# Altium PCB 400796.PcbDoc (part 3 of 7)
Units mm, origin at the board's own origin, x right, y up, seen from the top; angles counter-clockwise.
Board outline 53 x 53 mm, 6 copper layers (Top Layer, Mid Layer 1, Mid Layer 2, Mid Layer 3, Mid Layer 4, Bottom Layer), stack 1.494 mm thick; 319 components, 236 nets, 1249 pads, 2569 vias.
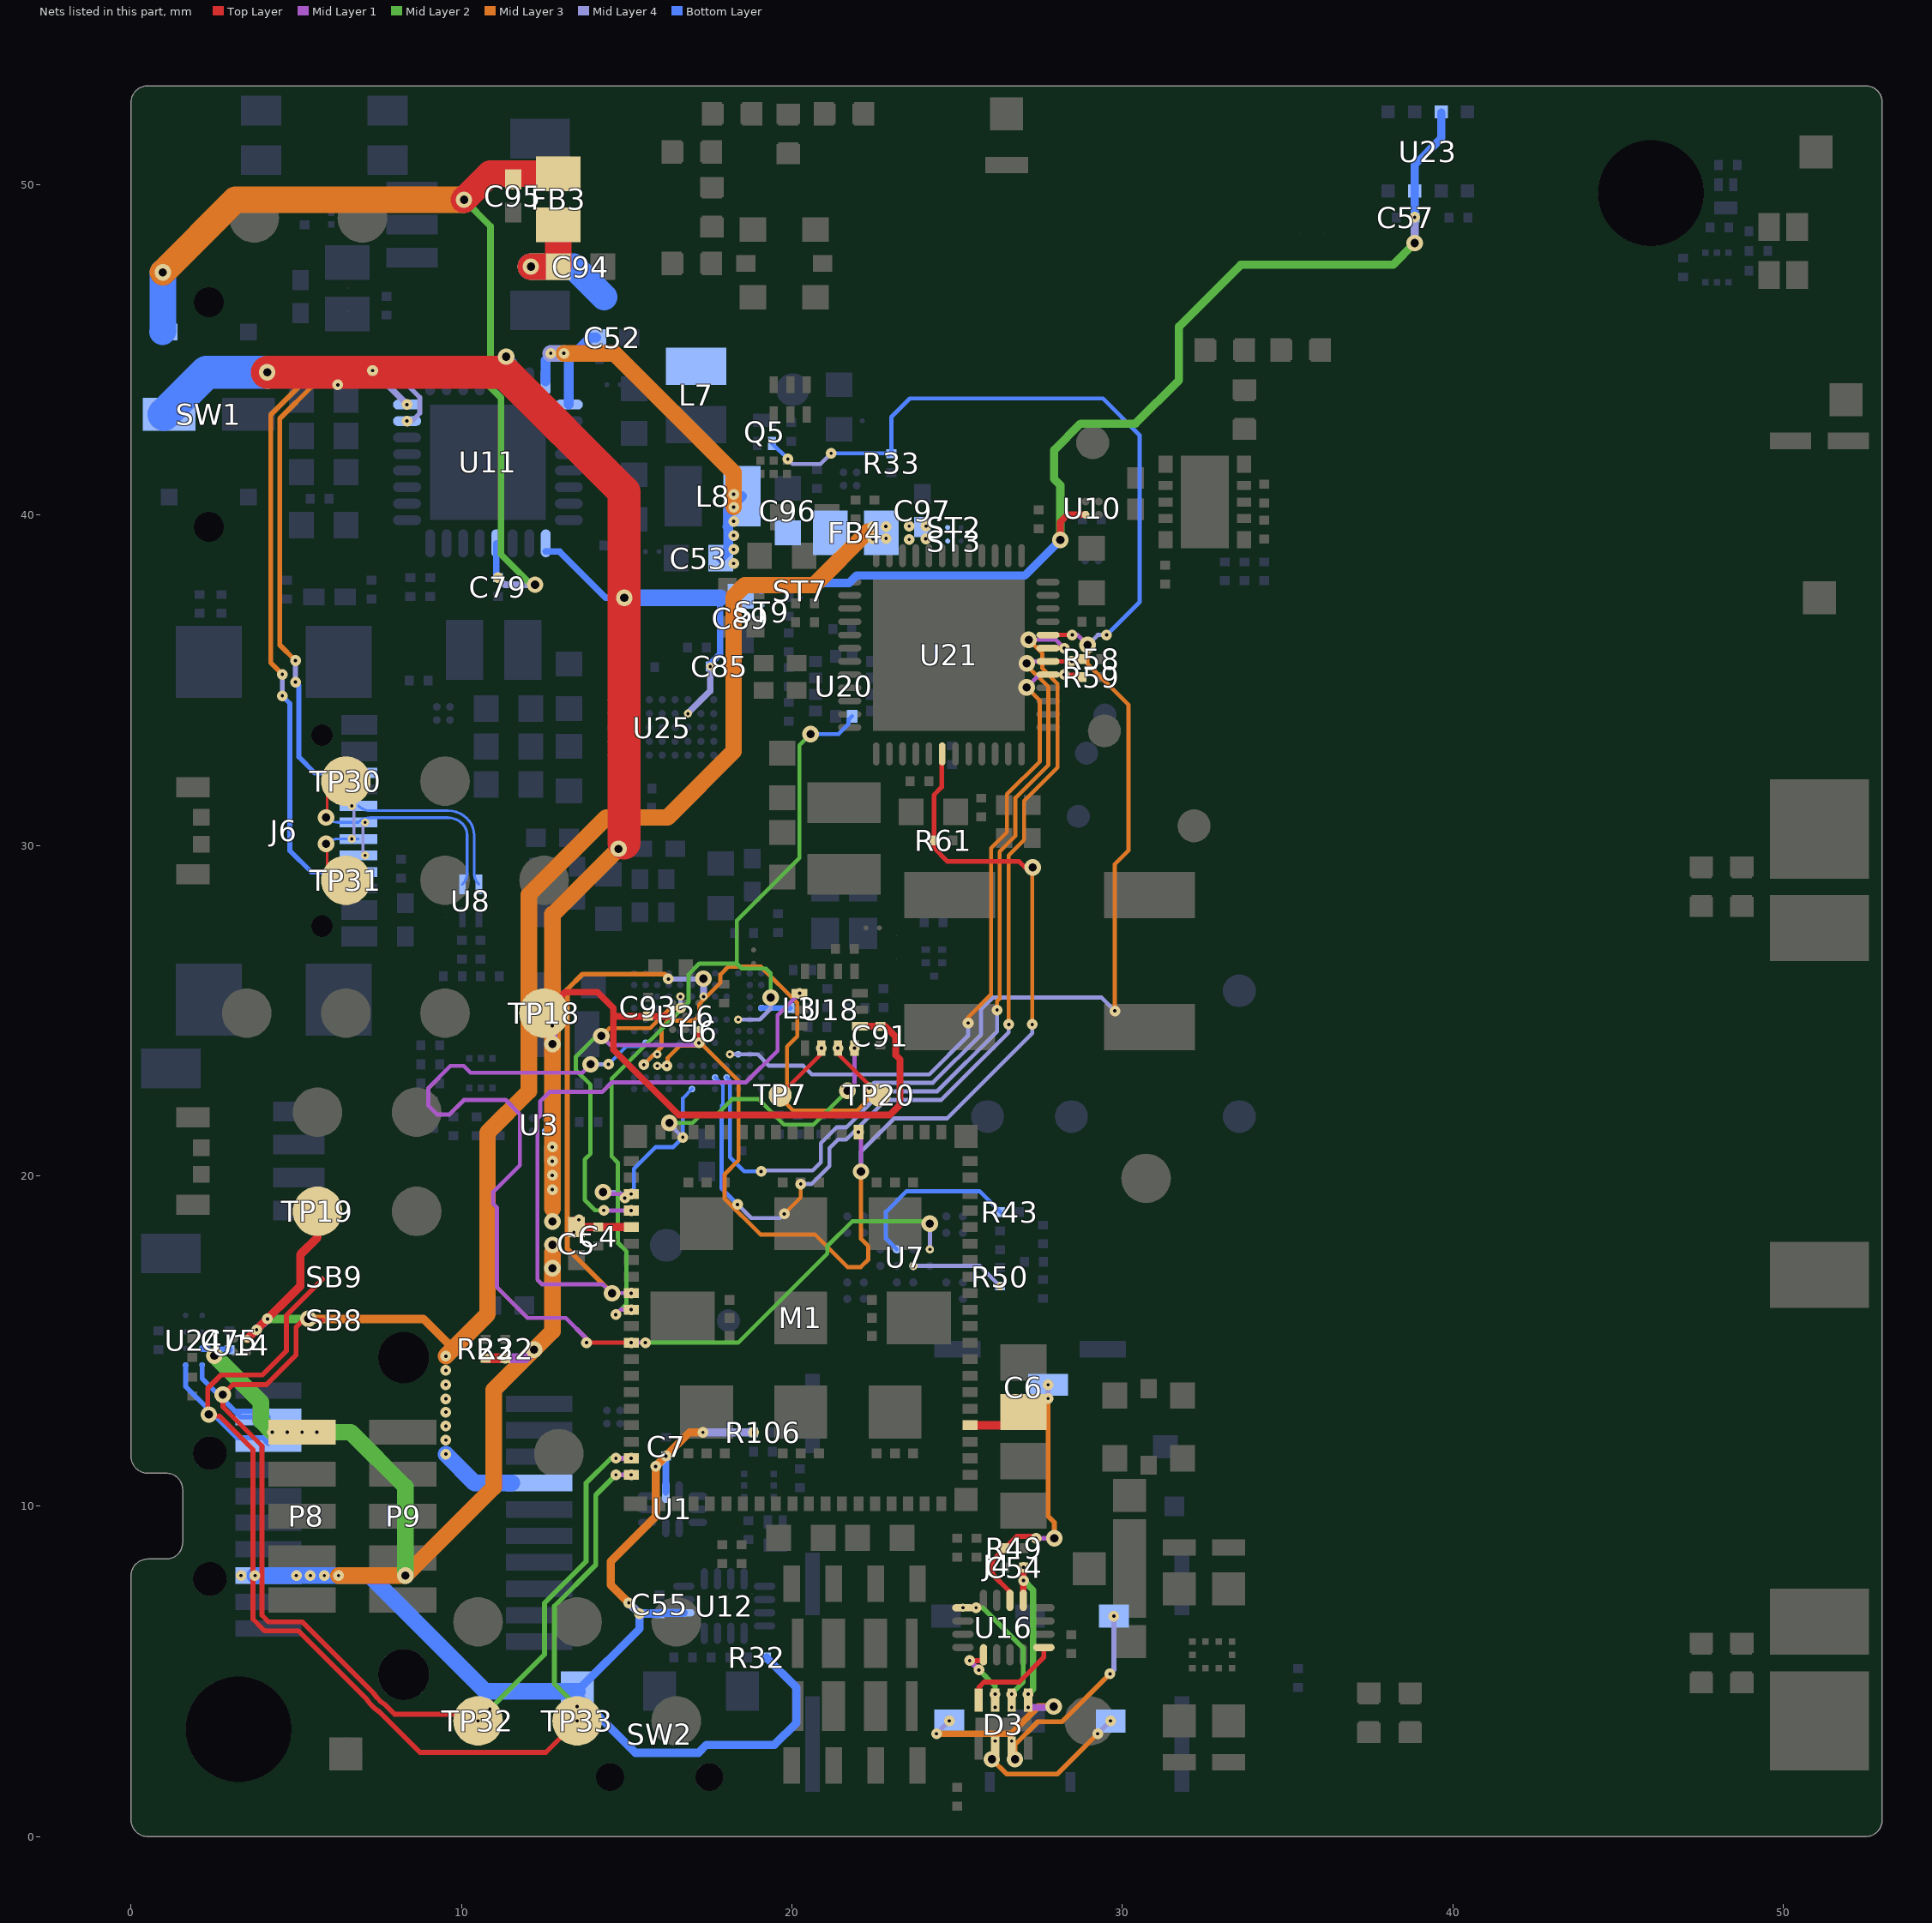
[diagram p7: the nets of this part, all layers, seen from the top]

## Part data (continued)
Z4 Z6: library part L0402-3n7-1950mA-30mΩ-LQW15AN3N7G80, "Inductor, 1950mA, ±2%, 30mΩ, Q=35", Manufacturer=Murata, Manufacturer Part Number=LQW15AN3N7G80D, Part number IPS=N.A., Part number NEMS=100300421, Supplier Part Number 1=81-LQW15AN3N7G80D
Z9: library part C0402-0.3p-HQ-Murata, "Capacitor, NP0, ±0.05pF, 50V", Manufacturer=Murata, Manufacturer Part Number=GJM1555C1HR30WB01D, Part number IPS=00000001777, Part number NEMS=100200433, Part number Norautron=N.A., Supplier Part Number 1=490-11248-1-ND
Z10: library part L0603-12n-750mA-71mΩ-LQW18AN12NG10, "Inductor, 750mA, ±2%, 71mΩ, Q=38", Manufacturer=Murata, Manufacturer Part Number=LQW18AN12NG10, Part number IPS=N.A., Part number NEMS=100300414, Supplier Part Number 1=490-6862-1-ND
Z11 Z32: library part C0402-N.C., "Not mounted", Manufacturer=N.A., Part number NEMS=100200105
Z12: library part L0402-N.C., "Not mounted", Manufacturer=N.A., Part number NEMS=100300037
Z21: library part L0402-2n8-1500mA-47mΩ-LQW15AN2N8G80, "Inductor, 1500mA, ±2%, 47mΩ, Q=27", Manufacturer=Murata, Manufacturer Part Number=LQW15AN2N8G80D, Part number IPS=N.A., Part number NEMS=100300422, Supplier Part Number 1=81-LQW15AN2N8G80D
Z22: library part L0402-2n5-Wirewound-Murata-LQW15AN2N5G80, "Inductor, 2100mA, ±2%, 30mΩ, Q=30", Manufacturer=Murata, Manufacturer Part Number=LQW15AN2N5G80D, Part number IPS=N.A., Part number NEMS=100300417, Supplier Part Number 1=LQW15AN2N5G80D-ND
Z31: library part L0402-3n8-Wirewound-Murata_HQ-LQW15AN3N8G80D, "3.8 nH Unshielded Drum Core, Wirewound Inductor 1.95 A 30mOhm Max 0402 (1005 Metric)", Manufacturer=Murata, Manufacturer Part Number=LQW15AN3N8G80D, Part number IPS=N.A., Part number NEMS=100300486, Supplier Part Number 1=490-LQW15AN3N8G80DTR-ND
Z33: library part L0402-9n0-Wirewound-Murata_HQ-LQW15AN6N0B80D, "6 nH Unshielded Drum Core, Wirewound Inductor 1.6 A 56mOhm Max 0402 (1005 Metric)", Manufacturer=Murata, Manufacturer Part Number=LQW15AN6N0B80D, Part number IPS=N.A., Part number NEMS=100300487, Supplier Part Number 1=490-17896-1-ND
Z34: library part C0402-0.4p-50V-NP0-GJM1555C1HR40WB01, "Capacitor, NP0, ±0.05pF, 50V", Manufacturer=Murata, Manufacturer Part Number=GJM1555C1HR40WB01D, Part number IPS=N.A., Part number NEMS=100200500, Supplier Part Number 1=490-11249-1-ND
Z35: library part C0402-1.8p-HQ-Murata, "Capacitor, C0G, ±0.05pF, 50V", Manufacturer=Murata, Manufacturer Part Number=GJM1555C1H1R8WB01D, Part number IPS=N.A., Part number NEMS=100200521, Supplier Part Number 1=490-11202-1-ND
Z36: library part L0603-N.C., "Not mounted", Manufacturer=N.A., Part number NEMS=100300069

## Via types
v1: diameter 0.325, hole 0.1, Mid Layer 4 to Bottom Layer, tented both sides, 675 vias
v2: diameter 0.325, hole 0.1, Top Layer to Mid Layer 1, tented both sides, 569 vias
v3: diameter 0.325, hole 0.1, Mid Layer 3 to Mid Layer 4, tented both sides, 384 vias
v4: diameter 0.5, hole 0.25, Mid Layer 1 to Mid Layer 4, tented both sides, 312 vias
v5: diameter 0.325, hole 0.1, Mid Layer 1 to Mid Layer 2, tented both sides, 265 vias
v6: diameter 0.5, hole 0.25, Top Layer to Bottom Layer, tented both sides, 175 vias
v7: diameter 0.25, hole 0.1, Mid Layer 4 to Bottom Layer, tented both sides, 105 vias
v8: diameter 0.325, hole 0.1, Top Layer to Mid Layer 1, tented top, 67 vias
v9: diameter 0.25, hole 0.1, Top Layer to Mid Layer 1, tented both sides, 17 vias

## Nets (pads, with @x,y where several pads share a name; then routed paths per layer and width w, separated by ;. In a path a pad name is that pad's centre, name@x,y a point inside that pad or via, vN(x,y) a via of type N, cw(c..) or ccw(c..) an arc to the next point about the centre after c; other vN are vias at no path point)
1V8: C79.1 C95.2 FB3.2 SW1.3 U11.12 | length 29.9
  Top Layer w0.8: v6(10.075,49.55) 10.866,50.341 FB3.2@12.931,50.341
  Mid Layer 2 w0.2: v6(10.075,49.55) 10.875,48.75 10.875,43.871 11.192,43.554 11.192,38.816 12.113,37.895 v4(12.226,37.895)
  Mid Layer 3 w0.8: v6(0.96,47.351) 3.159,49.55 v6(10.075,49.55)
  Mid Layer 4 w0.2: v1(11.1,38.11) 11.315,37.895 v4(12.226,37.895)
  Bottom Layer w0.2: C79.1@11.05,38.11 U11.12@11.05,39.15
  Bottom Layer w0.8: SW1.3@0.95,45.55 0.96,45.56 v6(0.96,47.351)
1V8_IND: C52.2 C94.2 FB3.1 L7.1 U11.1 | length 7.2
  Top Layer w0.8: v6(12.1,47.525) C94.2@12.931,47.525 FB3.1@12.931,48.791
  Bottom Layer w0.3: U11.1@13.25,43.35 13.25,44.723 13.904,45.377 C52.2@14.075,45.377
  Bottom Layer w0.8: v6(12.1,47.525) 13.4,47.525 14.318,46.607
1V8_SW: C4.1 C5.1 C7.1 C55.1 C57.2 C75.2 C85.1 C89.2 C91.2 C93.2 M1.65 P8.1 P9.3 R22.1 R23.1 R32.1 R106.1 ST7.1 ST9.1 SW1.2 SW2.3 TP18.1 U1.1 U3.A2 U10.A2 U11.9 U11.30 U12.14 U18.5 U23.2 U23.6 U24.C1 U25.C4 U26.B3 | length 166.2
  Top Layer w0.2: v6(28.125,39.25) 28.125,39.801 28.339,40.015 U10.A2@28.888,40.015
  Top Layer w0.203: TP18.1@12.5,24.927 13.135,25.563 14.117,25.563 14.596,25.084 14.596,24.835 ; C5.1@13.399,18.672 v2(13.552,18.672) ; C5.1@13.478,18.45 C5.1@13.478,18.523 ; U26.B3@16.388,24.831 C93.2@15.65,24.831 14.6,24.831 14.596,24.835 ; U18.5@22.056,24.529 C91.2@22.679,24.529 22.819,24.529 23.143,24.205 23.143,23.654 23.273,23.524 23.273,22.155 22.958,21.84 16.582,21.84 14.596,23.826 14.596,24.835
  Top Layer w0.25: C5.1@13.478,18.45 M1.65@15.142,18.45
  Top Layer w0.305: R23.1@10.723,14.48 v2(11.323,14.48) ; TP18.1@12.5,24.927 12.75,24.678 v2(12.75,24.542)
  Top Layer w1: v6(4.118,44.325) 11.3,44.325 14.925,40.7 v6(14.925,37.5) v6@14.925,30.075
  Mid Layer 1 w0.305: v2(11.323,14.48) 11.932,14.48 v4(12.193,14.741) ; v4(12.75,23.989) v2(12.75,24.542)
  Mid Layer 2 w0.25: v6(28.125,39.25) 28.125,40.908 27.939,41.094 27.939,41.972 28.737,42.77 30.4,42.77 31.714,44.084 31.714,45.711 33.586,47.583 38.194,47.583 v4(38.85,48.239)
  Mid Layer 2 w0.5: v6(2.518,14.561) 3.927,13.152 3.927,12.588 v5(4.275,12.24) v5(4.725,12.24) 6.646,12.24 8.3,10.586 v4(8.3,7.9)
  Mid Layer 3 w0.25: v3(15.062,7.075) 14.516,7.62 14.516,8.321 15.877,9.681 v3(15.877,11.206) 16.904,12.234 v3(17.307,12.234)
  Mid Layer 3 w0.5: v3(6.275,7.9) v4(8.3,7.9) 10.975,10.575 10.975,13.522 v4(12.193,14.741) 12.75,15.297 v4(12.75,17.202) v4@12.75,17.685 ; 12.75,19 12.75,27.925 ; 12.775,27.925 v6(14.75,29.9)
  Mid Layer 4 w0.2: v7@16.855,34.009 17.527,34.68 v7(17.527,35.42)
  Mid Layer 4 w0.25: v3(15.062,7.075) v1(15.386,6.75) ; v3(15.877,11.206) v1(16.186,11.516) ; v3(17.307,12.234) 17.309,12.232 v1(18.843,12.232) ; v4(38.85,48.239) v1(38.85,49.021)
  Bottom Layer w0.2: U11.9@12.55,38.9 12.964,38.9 14.364,37.5 v6(14.925,37.5) ; v7(17.527,35.42) 17.527,35.502 17.825,35.8 17.825,37.5
  Bottom Layer w0.203: U24.C1@2.15,14.775 2.304,14.775 v6(2.518,14.561) 2.698,14.74 C75.2@2.975,14.74 ; U1.1@16.186,10.425 v1(16.186,11.516)
  Bottom Layer w0.25: C55.1@16,6.75 v1(15.386,6.75) 15.386,6.286 SW2.3@13.5,4.4 13.5,4.298 15.265,2.534 17.17,2.534 17.412,2.775 19.471,2.775 20.137,3.442 20.137,4.512 R32.1@19.227,5.422 ; C55.1@16.05,6.775 U12.14@16.725,6.775 ; 19.073,37.734 19.289,37.949 21.728,37.949 21.958,38.18 27.055,38.18 v6(28.125,39.25) ; v1(38.85,49.021) U23.6@38.85,49.811 38.85,50.608 39.65,51.408 U23.2@39.65,52.195
  Bottom Layer w0.3: v6(11.35,44.8) 11.55,44.6 U11.30@11.55,44.05
  Bottom Layer w0.5: v1@12.75,20.45 v1(12.75,20.875) ; v6@14.95,37.5 17.825,37.5
  Bottom Layer w0.508: v1(3.75,7.9) P9.3@4.15,7.9 7.215,7.9 10.715,4.4 SW2.3@13.5,4.4
  Bottom Layer w1: SW1.2@1,43.05 2.275,44.325 v6(4.118,44.325)
  other v1: 3.325,7.9 12.75,19.585 12.75,20.015 12.75,20.445
  other v2: 5.175,12.24 5.625,12.24 13.401,18.293
  other v3: 5,7.9 5.425,7.9 5.85,7.9
  other v4: 12.75,17.912 12.75,18.621
  other v7: 16.855,33.995
2.4G_SW_CTRL: Q5.1 R33.2 U6.H10 U21.44 | length 56.5
  Top Layer w0.125: U21.44@27.75,36.375 v2(28.487,36.375)
  Mid Layer 1 w0.125: v2(28.487,36.375) 28.645,36.375 v4(28.95,36.07)
  Mid Layer 3 w0.125: v3(15.517,23.366) 16.059,23.907 16.059,24.496 16.262,24.699 17.048,24.699 17.193,24.844 17.193,25.199 17.836,25.842 17.836,26.098 18.071,26.334 19.063,26.334 20.164,25.233 20.164,24.227 19.85,23.913 19.85,22.161 20.032,21.98 21.976,21.98 22.337,22.341 v3(22.337,22.666) ; v4(28.95,36.07) 28.95,35.496 30.19,34.256 30.19,29.854 29.776,29.441 v3(29.776,24.994)
  Mid Layer 4 w0.125: v3(15.517,23.366) 15.831,23.68 v7(15.925,23.68) ; v1(19.875,41.7) 20.025,41.55 20.865,41.55 v1(21.189,41.874) ; v3(22.337,22.666) 22.49,22.819 24.268,22.819 25.725,24.275 25.725,25.042 26.079,25.396 29.374,25.396 v3(29.776,24.994) ; v4(28.95,36.07) 29.255,36.375 v1(29.525,36.375)
  Bottom Layer w0.125: Q5.1@19.4,42.175 v1(19.875,41.7) ; v1(21.189,41.874) 22.884,41.874 R33.2@22.935,41.824 ; R33.2@23.011,41.859 23.011,42.979 23.569,43.537 29.413,43.537 30.525,42.425 30.525,37.375 v1(29.525,36.375)
3V3: C97.2 FB4.2 P9.14 ST2.1 ST3.1 TP19.1 U14.A2 | length 46.2
  Top Layer w0.254: U14.A2@3.519,15.064 v2(3.797,15.342) 5.122,16.667 5.122,17.619 5.642,18.14 TP19.1@5.642,18.927
  Mid Layer 1 w0.254: v2(3.797,15.342) v5(4.125,15.67)
  Mid Layer 2 w0.254: v5(4.125,15.67) v4(5.361,15.67)
  Mid Layer 3 w0.254: v4(5.361,15.67) 8.848,15.67 9.747,14.772
  Mid Layer 3 w0.5: v3(9.525,14.54) 9.525,14.55 9.747,14.772 10.785,15.81 10.785,21.31 12.037,22.562 12.037,28.512 14.378,30.853 16.237,30.853 18.237,32.853 18.237,37.542 18.576,37.882 20.675,37.882 22.293,39.499 22.321,39.499
  Bottom Layer w0.5: v1(9.525,11.575) 10.4,10.7 P9.14@11.525,10.7
  other v1: 9.525,12 9.525,12.425 9.525,12.85 23.551,39.265 24.051,39.285 23.551,39.667 24.058,39.67
  other v3: 9.525,13.25 9.525,13.68 9.525,14.11 22.453,39.29 22.849,39.296 22.448,39.651 22.843,39.661
3V3_IND: C53.2 C96.2 FB4.1 L8.1 U11.32 | length 11.8
  Mid Layer 3 w0.5: v3(13.1,44.9) 14.625,44.9 18.237,41.288 v3(18.237,40.631) v3(18.237,40.244)
  Mid Layer 4 w0.5: v1(12.7,44.9) v3(13.1,44.9)
  Bottom Layer w0.3: U11.32@12.55,44.05 12.55,44.696 12.7,44.846 v1(12.7,44.9) ; C53.2@17.85,38.7 18.075,38.925 L8.1@18.075,40.165 ; 18.05,39.65 L8.1@18.07,39.67 ; 18.07,39.539 L8.1@18.07,39.67 ; L8.1@18.485,40.575 L8.1@18.075,40.165 ; L8.1@18.07,39.67 18.07,39.814 18.07,40.16 L8.1@18.075,40.165
  other v1: 18.237,38.538 18.237,38.964 18.237,39.389 18.237,39.814
4FF_1V8: C54.1 D3.5 J4.C1 U16.1 | length 10.6
  Top Layer w0.2: U16.1@27,7.15 C54.1@27,8.14
  Mid Layer 1 w0.15: v5(27.01,7.75) v2(27.01,8.15)
  Mid Layer 1 w0.2: v5(27.15,4.31) v9(27.15,3.91) v4@27.925,3.91
  Mid Layer 2 w0.2: v5(27.01,7.75) 27.3,7.46 27.3,4.46 v5(27.15,4.31)
  Mid Layer 3 w0.2: v3(24.376,3.111) 26.636,3.111 27.46,3.935 v4(27.925,3.935)
  Mid Layer 4 w0.15: v3(24.376,3.111) v1(24.765,3.5)
4FF_CLK: D3.7 U16.9 | length 2.3
  Top Layer w0.15: v2(25.38,5.325) 25.381,5.326 25.768,5.326 25.8,5.359 U16.9@25.8,5.5
  Mid Layer 1 w0.15: v2(25.38,5.325) v5(25.662,5.042) ; v9(26.15,3.91) v5(26.15,4.31)
  Mid Layer 2 w0.15: v5(25.662,5.042) 26.15,4.555 v5(26.15,4.31)
4FF_DETECT: J4.DSW R49.1 U16.2 | length 8.3
  Top Layer w0.15: R49.1@26.365,8.65 26.077,8.362 26.077,7.926 26.565,7.438 26.565,7.419 26.6,7.384 U16.2@26.6,7.15 ; R49.1@26.44,8.725 26.804,9.089 27.359,9.089 27.388,9.06 v2(27.388,9.028)
  Mid Layer 1 w0.15: v2(27.388,9.028) v4(27.941,9.028)
  Mid Layer 3 w0.15: v3(27.755,13.258) 27.755,9.696 27.941,9.511 v4(27.941,9.028)
  Mid Layer 4 w0.15: v3(27.755,13.258) v1(27.755,13.675)
4FF_IO: D3.6 U16.5 | length 4.3
  Mid Layer 1 w0.15: v9(25.175,6.925) v5(25.575,6.925) ; v9(26.65,3.91) v5(26.65,4.31)
  Mid Layer 2 w0.15: v5(25.575,6.925) 25.775,6.925 27,5.7 27,4.673 26.65,4.323 v5(26.65,4.31)
4FF_RST: D3.8 U16.13 | length 3.3
  Top Layer w0.15: D3.8@25.65,3.91 D3.8@25.65,4.125 25.65,4.51 25.815,4.675 26.875,4.675 27.625,5.425 U16.13@27.625,5.725
ADXL367_INT: M1.70 U6.E3 U20.5 | length 26.5
  Mid Layer 1 w0.125: v5(14.667,15.798) 14.82,15.95 v2(15.138,15.95)
  Mid Layer 2 w0.125: v5(14.667,15.798) 14.994,16.124 14.994,17.715 14.732,17.977 14.732,20.398 14.544,20.586 14.544,22.939 16.874,25.269 16.874,26.109 17.19,26.425 18.334,26.425 ; v4(19.359,25.4) 19.359,26.136 19.218,26.277 18.482,26.277 18.334,26.425 ; v6(20.561,33.375) 20.225,33.039 20.225,29.625 18.334,27.734 18.334,26.425
  Mid Layer 4 w0.125: v7(18.375,24.73) 19.026,24.73 19.359,25.063 v4(19.359,25.4)
  Bottom Layer w0.125: v6(20.561,33.375) 21.412,33.375 21.711,33.674 21.711,33.801 U20.5@21.825,33.915
ANT: L3.2 U6.D1 | length 0.9
  Bottom Layer w0.165: U6.D1@19.075,25.08 L3.2@19.939,25.08
ASCL: TP20.1 U18.3 | length 1.9
  Top Layer w0.125: v2(21.393,23.866) 21.393,23.694 TP20.1@22.643,22.444
ASDA: TP7.1 U18.2 | length 1.9
  Top Layer w0.125: TP7.1@19.643,22.444 20.893,23.694 v2(20.893,23.866)
BMI270_CS: M1.69 U6.C6 U18.12 | length 32.7
  Mid Layer 1 w0.125: v2(15.138,16.45) 14.556,16.45 v4(14.554,16.447) 14.285,16.715 12.437,16.715 12.297,16.854 12.297,21.738 12.387,21.827 12.387,22.263 12.666,22.542 14.256,22.542 14.544,22.83 18.608,22.83 19.568,23.789 19.568,24.866 v2(20.231,25.529)
  Mid Layer 2 w0.203: v4@17.167,25.971 v4@17.193,25.971
  Mid Layer 3 w0.152: v4(14.554,16.447) 13.201,17.799 13.201,25.646 13.663,26.108 16.139,26.108 16.159,26.088
  Mid Layer 4 w0.152: v3(16.261,25.961) 17.182,25.961 v4@17.193,25.971
  Mid Layer 4 w0.203: v4@17.18,25.958 17.325,25.814 v7(17.325,25.43)
  other v4: 17.32,25.971
BMI270_INT: M1.63 U6.L7 U18.4 | length 14.4
  Mid Layer 1 w0.125: v4(14.283,19.509) 14.342,19.45 v2(15.138,19.45) ; v4(21.681,22.575) 21.893,22.787 v2(21.893,23.866)
  Mid Layer 2 w0.125: v4(16.291,21.604) 16.99,21.604 17.214,21.828 17.692,21.828 18.185,22.321 18.994,22.321 19.761,21.554 20.66,21.554 v4(21.681,22.575)
  Mid Layer 4 w0.125: v4(14.283,19.509) 14.762,19.509 v1(14.943,19.328) ; v4(16.291,21.604) 16.291,21.571 v1(16.698,21.165)
  Bottom Layer w0.105: 16.698,21.858 16.698,22.353 U6.L7@16.975,22.63
  Bottom Layer w0.125: v1(14.943,19.328) 15.216,19.601 15.216,20.214 15.87,20.869 16.402,20.869 v1(16.698,21.165) 16.698,21.819
BMM350_INT: M1.64 U6.C8 U26.A1 | length 13.8
  Top Layer w0.125: v2(17.188,24.025) U26.A1@17.188,24.431
  Mid Layer 1 w0.125: v4(14.235,24.234) 14.511,23.958 17.121,23.958 v2(17.188,24.025) ; v5(14.304,18.956) 14.31,18.95 v2(15.138,18.95)
  Mid Layer 2 w0.125: v4(14.235,24.234) 14.086,24.234 13.46,23.608 13.46,23.198 13.903,22.755 13.903,20.674 13.732,20.503 13.732,19.267 14.044,18.956 v5(14.304,18.956)
  Mid Layer 3 w0.125: v4(14.235,24.234) 14.475,24.474 15.716,24.474 16.318,25.077 v3(16.631,25.077)
  Mid Layer 4 w0.125: v7(16.625,25.43) 16.625,25.083 v3(16.631,25.077)
BUCKEN: M1.47 R61.1 U6.J10 U21.30 | length 34.6
  Top Layer w0.14: U21.30@24.55,32.775 24.539,32.764 24.539,32.471 24.531,32.464 24.531,31.767 24.302,31.537 R61.1@24.302,30.157 24.302,29.923 24.7,29.525 26.869,29.525 v6@27.055,29.339
  Mid Layer 1 w0.125: v2(22.013,21.325) 22.089,21.249 v4(22.089,20.131)
  Mid Layer 3 w0.125: v3@16.238,23.358 16.238,23.571 16.616,23.949 17.31,23.949 18.386,22.873 18.386,20.474 17.963,20.051 17.963,19.308 19.045,18.226 20.694,18.226 21.682,17.238 22.088,17.238 22.31,17.461 22.31,17.875 22.089,18.097 v4(22.089,20.131) ; v3(27.275,24.584) 27.275,29.33 v6(27.284,29.339)
  Mid Layer 4 w0.125: v7(15.925,23.33) 16.21,23.33 v3(16.213,23.332) v3@16.238,23.358 ; v4(22.089,20.131) 22.089,20.731 23.102,21.744 24.699,21.744 27.275,24.32 v3(27.275,24.584)
CC1: J6.A5 U11.23 | length 22.1
  Mid Layer 3 w0.15: 4.225,37.948 4.225,39.152 ; 4.225,37.948 4.225,35.534 v3(4.576,35.183) ; 4.225,39.152 4.225,43.041 5.562,44.378 v3(7.309,44.378)
  Mid Layer 4 w0.15: v1(4.576,34.533) v3(4.576,35.183) ; v3(7.309,44.378) 7.927,44.378 8.737,43.568 8.737,43.085 8.502,42.85 v1(8.35,42.85)
  Bottom Layer w0.15: v1(4.576,34.533) 4.805,34.304 4.805,29.845 5.45,29.2 J6.A5@6.88,29.2
CC2: J6.B5 U11.24 | length 17
  Mid Layer 3 w0.15: v3(4.975,35.6) 4.5,36.075 4.5,38.062 4.5,39.038 4.5,42.927 5.52,43.948 v3(6.254,43.948)
  Mid Layer 4 w0.15: v1(4.975,34.95) v3(4.975,35.6)
  Mid Layer 4 w0.2: v3(6.254,43.948) 7.752,43.948 v1(8.35,43.35)
  Bottom Layer w0.15: v1(4.975,34.95) 5.08,34.845 5.08,32.677 5.557,32.2 J6.B5@6.88,32.2
CLK: D3.2 J4.C3 | length 4.9
  Mid Layer 1 w0.15: v4@26.15,2.535 v9(26.15,2.89) v9@26.15,2.94
  Mid Layer 3 w0.15: v4(26.05,2.34) 26.5,1.89 28.035,1.89 v3(29.256,3.111)
  Mid Layer 4 w0.15: v3(29.256,3.111) v1(29.645,3.5)
COEX_GRANT: U6.K5 U21.43 | length 30
  Top Layer w0.125: U21.43@27.75,35.975 v2(28.243,35.975)
  Mid Layer 1 w0.125: v4(27.166,36.229) 27.989,36.229 v2(28.243,35.975)
  Mid Layer 3 w0.125: v3(19.77,18.849) 20.265,19.344 v3(20.265,19.753) ; v3(26.562,24.584) 26.562,29.704 27.029,30.171 27.029,31.351 28.041,32.363 28.041,34.897 27.58,35.359 27.58,35.816 v4(27.166,36.229)
  Mid Layer 4 w0.125: v1(18.356,19.134) 18.768,18.722 19.643,18.722 v3(19.77,18.849) ; v3(20.265,19.753) 20.595,19.753 21.136,20.295 21.136,20.844 21.392,21.1 21.636,21.1 22.833,22.297 24.513,22.297 26.562,24.346 v3(26.562,24.584)
  Bottom Layer w0.105: U6.K5@17.675,22.98 17.917,22.738 17.917,22.171 17.872,22.126 17.872,21.819
  Bottom Layer w0.125: 17.872,21.819 17.872,19.618 v1(18.356,19.134)
COEX_REQ: R58.1 U6.K4 U21.42 | length 27.3
  Top Layer w0.125: U21.42@27.75,35.575 v2(28.471,35.575) 28.703,35.575 R58.1@28.778,35.65
  Mid Layer 1 w0.125: v4(27.109,35.515) 27.169,35.575 v2(28.471,35.575)
  Mid Layer 3 w0.125: v3(26.212,25.023) 26.212,25.29 26.288,25.367 26.288,29.818 26.763,30.294 26.763,31.444 27.762,32.443 27.762,34.797 27.109,35.45 v4(27.109,35.515)
  Mid Layer 4 w0.125: v1(19.069,20.136) 19.096,20.163 20.631,20.163 20.877,20.409 20.877,20.994 21.348,21.465 21.641,21.465 22.733,22.558 24.398,22.558 26.212,24.371 v3(26.212,25.023)
  Bottom Layer w0.105: U6.K4@18.025,22.98 18.125,22.879 18.125,21.819
  Bottom Layer w0.125: 18.125,21.819 18.125,20.563 18.553,20.136 v1(19.069,20.136)
COEX_STATUS: R59.1 U6.H3 U21.41 | length 22.2
  Top Layer w0.125: U21.41@27.75,35.175 v2(28.243,35.175) 28.703,35.175 R59.1@28.778,35.1
  Mid Layer 1 w0.125: v4(27.104,34.79) 27.489,35.175 v2(28.243,35.175)
  Mid Layer 3 w0.125: v3(25.334,24.629) 25.334,24.8 26.027,25.493 26.027,29.924 26.509,30.406 26.509,31.553 27.503,32.547 27.503,34.392 v4(27.104,34.79)
  Mid Layer 4 w0.125: v7(18.121,23.68) 18.965,23.68 19.311,23.333 20.34,23.333 20.605,23.069 24.157,23.069 25.334,24.246 v3(25.334,24.629)
  Bottom Layer w0.125: v7(18.121,23.68) U6.H3@18.375,23.68
D:J6_N: J6.A7 J6.B7 TP30.1 U8.2 | length 8.2
  Top Layer w0.083: v6(5.9,30.85) 5.929,30.879 TP30.1@5.929,31.879
  Mid Layer 4 w0.083: v7@7.018,29.7 v7@7.018,30.7
  Bottom Layer w0.083: v6(5.9,30.85) ccw(c6.262,31.212) 6.262,30.7 J6.A7@6.88,30.7 cw(c7.23,30.35) 7.23,30.845 9.588,30.845 cw(c9.588,30.229) 10.024,30.664 cw(c9.668,30.308) 10.172,30.308 10.172,29.173 cw(c9.677,29.173) U8.2@10.027,28.823
  other v7: 7.08,29.7 7.08,30.7
D:J6_P: J6.A6 J6.B6 TP31.1 U8.3 | length 8.5
  Top Layer w0.083: v6(5.9,30.05) 5.929,30.021 TP31.1@5.929,29.021
  Mid Layer 4 w0.083: v7@6.742,30.2 v7@6.742,31.2
  Bottom Layer w0.083: v6(5.9,30.05) cw(c6.262,29.688) 6.262,30.2 J6.A6@6.88,30.2 ; J6.B6@6.88,31.2 ccw(c7.23,31.55) 7.23,31.055 9.591,31.055 cw(c9.591,30.235) 10.171,30.815 10.174,30.812 cw(c9.673,30.31) 10.382,30.31 10.382,29.173 ccw(c10.877,29.173) U8.3@10.527,28.823
  other v7: 6.68,30.2 6.68,31.2
DATA: D3.3 J4.C7 | length 6.4
  Mid Layer 1 w0.15: v4@26.65,2.535 v9(26.65,2.89) v9@26.65,2.94
  Mid Layer 3 w0.15: v4(26.75,2.34) 26.75,2.78 27.444,3.474 28.174,3.474 v3(29.625,4.925)
  Mid Layer 4 w0.15: v3(29.625,4.925) 29.745,5.045 v1(29.745,6.67)
DEC0: C6.1 M1.24 | length 1.8
  Top Layer w0.254: M1.24@25.392,12.45 26.605,12.45 C6.1@27.006,12.851
EXP_BOARD.PIN1: M1.80 P9.8 SB9.1 TP33.1 U24.D2 | length 37.8
  Top Layer w0.15: v6(2.35,12.775) 2.32,12.805 2.32,13.569 2.722,13.971 3.971,13.971 4.703,14.703 4.703,15.78 5.794,16.871 ; v6@2.399,12.726 2.673,12.726 3.685,11.715 3.685,6.583 3.963,6.305 4.043,6.225 5.065,6.225 7.121,4.169 ccw(c8.25,4.9) 7.505,3.78 cw(c7.424,3.654) 7.53,3.76 8.74,2.55 12.55,2.55 v2(13.5,3.5)
  Mid Layer 1 w0.15: v2(13.5,3.5) v5(13.5,3.936) ; v5(14.674,10.95) v2(15.138,10.95)
  Mid Layer 2 w0.15: v5(13.5,3.936) 12.811,4.625 12.811,6.973 14.061,8.224 14.061,10.337 v5(14.674,10.95)
  Bottom Layer w0.15: U24.D2@1.65,14.275 1.65,13.625 3.2,12.075 3.975,12.075 P9.8@4.15,11.9
EXP_BOARD.PIN2: M1.79 P9.9 SB8.1 TP32.1 U24.D1 | length 34.3
  Top Layer w0.15: v6(2.775,13.375) 3.079,13.679 4.098,13.679 4.995,14.576 4.995,15.42 5.21,15.635 SB8.1@5.794,15.635 ; v6@2.78,13.37 2.78,13.008 3.96,11.829 3.96,6.697 4.157,6.5 5.179,6.5 5.223,6.456 7.325,4.354 7.337,4.341 ccw(c8.25,4.9) 7.691,3.987 7.704,3.975 7.979,3.7 10.3,3.7 v2(10.5,3.5)
  Mid Layer 1 w0.15: v2(10.5,3.5) v5(10.859,3.859) ; v5(14.674,11.45) v2(15.138,11.45)
  Mid Layer 2 w0.15: v5(10.859,3.859) 12.513,5.513 12.513,7.067 13.774,8.328 13.774,10.703 14.521,11.45 v5(14.674,11.45)
  Bottom Layer w0.15: U24.D1@2.15,14.275 2.15,13.862 3.312,12.7 P9.9@4.15,12.7 3.975,12.875 3.15,12.875 v6@2.712,13.313
FLASH_C\S\: M1.72 U6.G11 U7.C4 | length 33.1
  Top Layer w0.125: v2(13.784,14.95) v2(15.138,14.95)
  Mid Layer 1 w0.125: v2(13.784,14.95) 13.784,15.07 13.156,15.698 11.997,15.698 11.075,16.619 11.075,19.033 10.956,19.152 10.956,19.511 11.768,20.323 11.768,21.866 11.335,22.298 10.073,22.298 9.634,21.859 9.257,21.859 8.995,22.121 8.995,22.656 9.669,23.329 10.066,23.329 10.271,23.124 13.655,23.124 v4(13.909,23.378) ; v2(15.138,14.95) v5(15.565,14.95)
  Mid Layer 2 w0.125: v4@13.903,23.384 v4(13.909,23.378)
  Mid Layer 2 w0.127: v5(15.565,14.95) 18.372,14.95 21.072,17.65 21.072,17.872 21.823,18.623 24.104,18.623 v4(24.175,18.552)
  Mid Layer 4 w0.125: v4(13.909,23.378) v1(14.447,23.378)
  Mid Layer 4 w0.127: v7(24.175,17.775) v4(24.175,18.552)
  Bottom Layer w0.105: v1(14.447,23.378) 14.991,23.922 15.466,23.922 U6.G11@15.575,24.03
FLASH_R\E\S\E\T\: R50.1 U7.D3 | length 2.9
  Mid Layer 4 w0.125: v7(23.675,17.275) 25.69,17.275 v7(26.301,16.663)
FLASH_W\P\: R43.1 U7.E4 | length 5.3
  Bottom Layer w0.125: U7.E4@23.175,17.775 22.844,18.106 22.844,18.91 23.469,19.536 25.679,19.536 R43.1@26.315,18.9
